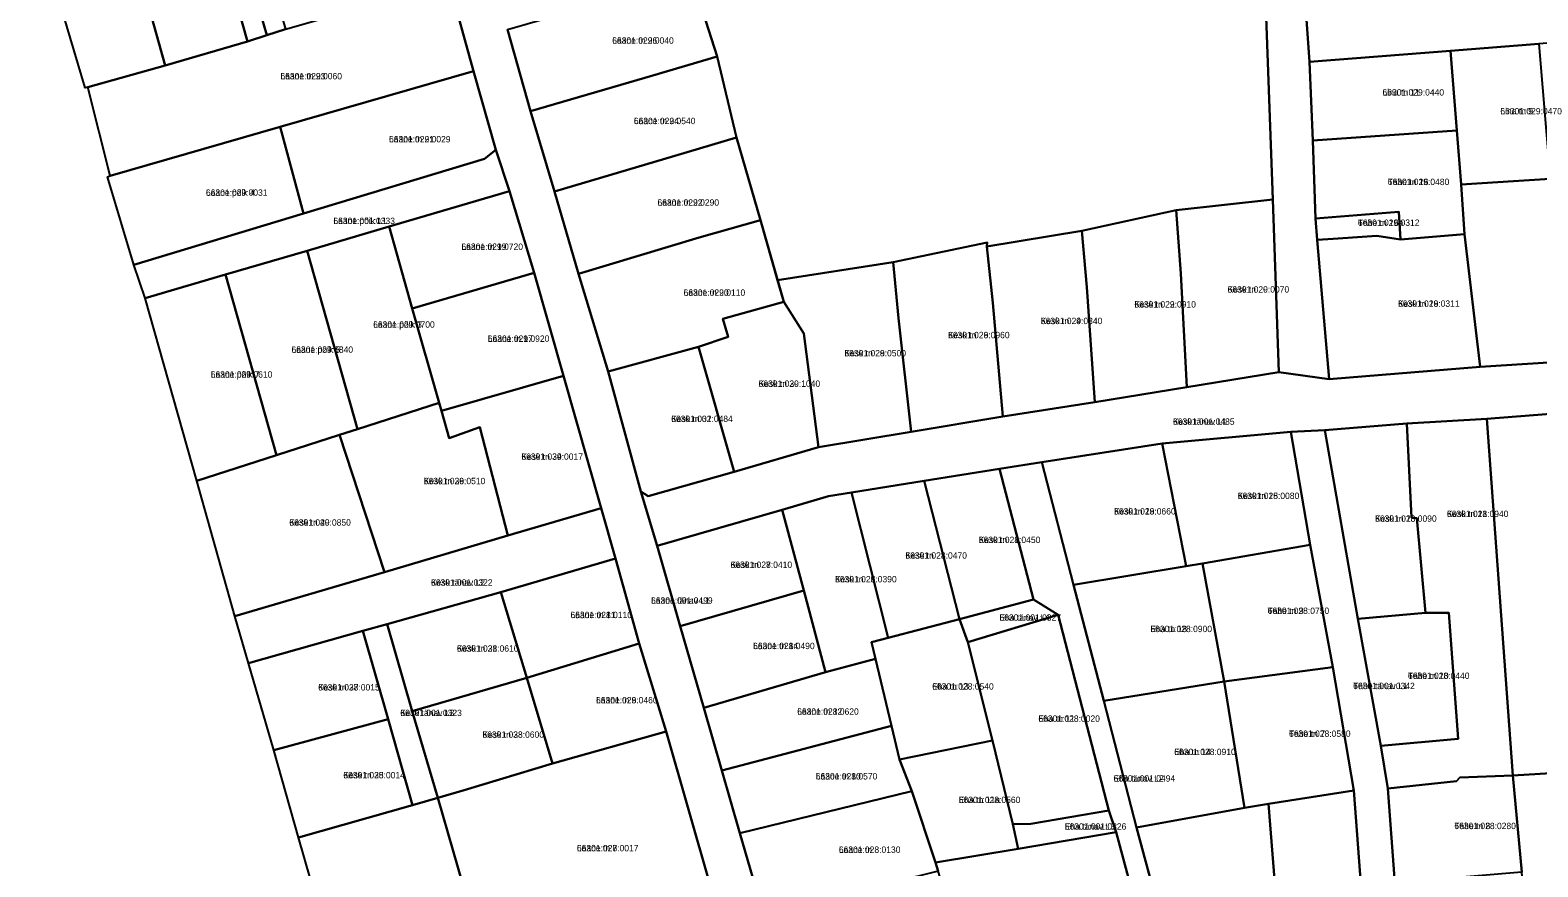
# Model space of a CAD drawing. Extents: x 632278 to 636344, y 6578401 to 6583362.
# Drawn here: x 632786.9 to 633142, y 6582179.7 to 6582376.8 of the extents above; entities that cross this region are included whole.
import ezdxf

# ---------------------------------------------------------------- set-up
doc = ezdxf.new("R2010")
doc.units = 0
for name, color, linetype in [('L_AADRESS', 7, 'Continuous'), ('PIIR', 7, 'Continuous'), ('TUNNUS', 7, 'Continuous')]:
    doc.layers.add(name, color=color, linetype=linetype)

msp = doc.modelspace()

# ---------------------------------------------------------------- linework, layer by layer
at = {"layer": 'PIIR'}
for points in [[(633075.2, 6582463.43), (633077.8, 6582386.33), (633070.2, 6582386.4), (633070.38, 6582382.02), (633077.94, 6582382.05), (633079.64, 6582336.91), (633056.87, 6582334.44), (633034.63, 6582329.54), (633012.24, 6582325.89), (633012.31, 6582326.81), (632990.17, 6582322.14), (632962.98, 6582317.93), (632958.95, 6582332.08), (632953.33, 6582351.51), (632948.72, 6582370.57), (632942.69, 6582389.52), (632937.03, 6582408.7), (632931.66, 6582427.68), (632925.7, 6582446.5), (632956.46, 6582453.19)], [(633075.2, 6582463.43), (633083.8, 6582464.53), (633084.6, 6582446.14), (633085.71, 6582421.36), (633086.82, 6582396.6), (633087.54, 6582379.34), (633088.25, 6582369.37), (633089.06, 6582350.85), (633089.65, 6582332.46), (633090.09, 6582327.4), (633092.89, 6582294.58), (633081.06, 6582296.22), (633079.64, 6582336.91), (633077.94, 6582382.05), (633077.8, 6582386.33)], [(632825.72, 6582418.14), (632830.04, 6582419.35), (632842.66, 6582375.6), (632838.14, 6582374.11)], [(632834.48, 6582420.6), (632847.1, 6582377.07), (632842.66, 6582375.6), (632830.04, 6582419.35)], [(632806.48, 6582412.41), (632825.72, 6582418.14), (632838.13, 6582374.11), (632818.75, 6582368.45)], [(632786.95, 6582406.91), (632806.48, 6582412.41), (632818.75, 6582368.45), (632800.56, 6582363.41), (632799.87, 6582363.22)], [(633087.54, 6582379.34), (633122.51, 6582382.07), (633141.41, 6582383.64), (633160.25, 6582385.06), (633179.47, 6582386.64), (633198.45, 6582388.1), (633235.16, 6582391.14), (633226.94, 6582379.94), (633205, 6582378.31), (633183.06, 6582376.69), (633161.16, 6582375.07), (633142.22, 6582373.59), (633121.45, 6582371.97), (633088.25, 6582369.37)], [(632800.56, 6582363.41), (632818.75, 6582368.45), (632838.13, 6582374.11), (632842.66, 6582375.6), (632847.1, 6582377.07), (632866.05, 6582382.47), (632866.64, 6582382.67), (632885.63, 6582387.98), (632891.4, 6582367.16), (632845.82, 6582354.06), (632805.79, 6582342.47)], [(632942.69, 6582389.52), (632948.72, 6582370.57), (632933.57, 6582366.11), (632904.77, 6582357.74), (632899.39, 6582376.93)], [(633122.93, 6582353.15), (633121.45, 6582371.97), (633142.22, 6582373.59), (633144.92, 6582341.77), (633123.93, 6582340.48)], [(632904.77, 6582357.74), (632933.57, 6582366.11), (632948.72, 6582370.57), (632953.33, 6582351.51), (632938.77, 6582347.18), (632910.47, 6582338.77)], [(633088.25, 6582369.37), (633121.45, 6582371.97), (633122.93, 6582353.15), (633089.06, 6582350.85)], [(632891.4, 6582367.16), (632896.61, 6582348.6), (632893.94, 6582346.51), (632851.32, 6582333.61), (632845.82, 6582354.06)], [(632845.82, 6582354.06), (632851.32, 6582333.61), (632811.34, 6582321.53), (632805.17, 6582342.29), (632805.79, 6582342.47)], [(633089.06, 6582350.85), (633122.93, 6582353.15), (633123.93, 6582340.48), (633124.72, 6582328.72), (633109.71, 6582327.48), (633109.27, 6582334.03), (633089.65, 6582332.46)], [(632811.34, 6582321.53), (632851.32, 6582333.61), (632893.94, 6582346.51), (632896.61, 6582348.6), (632899.87, 6582338.85), (632871.5, 6582330.53), (632852.15, 6582324.86), (632832.98, 6582319.24), (632814.01, 6582313.68)], [(632910.47, 6582338.77), (632938.77, 6582347.18), (632953.33, 6582351.51), (632958.95, 6582332.08), (632944.54, 6582327.94), (632916.11, 6582319.43)], [(633124.72, 6582328.72), (633123.93, 6582340.48), (633144.92, 6582341.77), (633163.87, 6582342.93), (633164.29, 6582336.96), (633166.86, 6582299.97), (633128.48, 6582297.49)], [(632871.5, 6582330.53), (632899.87, 6582338.85), (632905.62, 6582319.67), (632876.94, 6582311.27)], [(633056.87, 6582334.44), (633057.98, 6582319.51), (633059.37, 6582292.7), (633037.67, 6582289.17), (633035.82, 6582316.25), (633034.63, 6582329.54)], [(633079.64, 6582336.91), (633081.06, 6582296.22), (633059.37, 6582292.7), (633057.98, 6582319.51), (633056.87, 6582334.44)], [(633090.09, 6582327.4), (633089.65, 6582332.46), (633109.27, 6582334.03), (633109.71, 6582327.48), (633104.1, 6582328.35), (633093.85, 6582327.63)], [(632852.15, 6582324.86), (632871.5, 6582330.53), (632876.94, 6582311.27), (632883.31, 6582289.02), (632864.03, 6582282.82)], [(632916.11, 6582319.43), (632944.54, 6582327.94), (632958.95, 6582332.08), (632964.43, 6582312.83), (632950.05, 6582308.81), (632951.3, 6582304.54), (632944.39, 6582302.26), (632923.06, 6582296.42)], [(633034.63, 6582329.54), (633035.82, 6582316.25), (633037.67, 6582289.17), (633016.06, 6582285.79), (633013.67, 6582312.62), (633012.24, 6582325.89)], [(633092.89, 6582294.58), (633090.09, 6582327.4), (633093.85, 6582327.63), (633104.1, 6582328.35), (633109.71, 6582327.48), (633124.72, 6582328.72), (633128.48, 6582297.49)], [(632832.98, 6582319.24), (632852.15, 6582324.86), (632864.03, 6582282.82), (632859.83, 6582281.47), (632844.98, 6582276.7)], [(633012.31, 6582326.81), (633012.24, 6582325.89), (633013.67, 6582312.62), (633016.06, 6582285.79), (632994.46, 6582282.19), (632991.47, 6582308.98), (632990.17, 6582322.14)], [(632990.17, 6582322.14), (632991.47, 6582308.98), (632994.46, 6582282.19), (632972.6, 6582278.59), (632969.19, 6582305.33), (632964.43, 6582312.83), (632962.98, 6582317.93)], [(632814.01, 6582313.68), (632832.98, 6582319.24), (632844.98, 6582276.7), (632826.17, 6582270.66)], [(632883.31, 6582289.02), (632876.94, 6582311.27), (632905.62, 6582319.67), (632912.56, 6582295.38), (632883.84, 6582287.12)], [(632944.39, 6582302.26), (632951.3, 6582304.54), (632950.05, 6582308.81), (632964.43, 6582312.83), (632969.19, 6582305.33), (632972.6, 6582278.59), (632952.77, 6582272.75)], [(632930.8, 6582268.16), (632923.06, 6582296.42), (632944.39, 6582302.26), (632952.77, 6582272.75), (632932.49, 6582267.03)], [(632883.84, 6582287.12), (632912.56, 6582295.38), (632921.43, 6582264.25), (632899.47, 6582257.75), (632892.85, 6582283.28), (632885.66, 6582280.75)], [(632859.83, 6582281.47), (632864.03, 6582282.82), (632883.31, 6582289.02), (632883.84, 6582287.12), (632885.66, 6582280.75), (632892.85, 6582283.28), (632899.47, 6582257.75), (632870.39, 6582249.16)], [(633130.03, 6582285.3), (633168.04, 6582288.21), (633174.79, 6582203.63), (633136.14, 6582201.28)], [(633122.89, 6582199.92), (633106.71, 6582198.2), (633105.06, 6582208.24), (633123.23, 6582209.86), (633121.03, 6582239.56), (633115.58, 6582239.54), (633113.49, 6582261.84), (633112.25, 6582262.05), (633111.15, 6582284.13), (633130.03, 6582285.3), (633136.14, 6582201.28), (633123.65, 6582200.81)], [(632844.98, 6582276.7), (632859.83, 6582281.47), (632870.39, 6582249.16), (632835.19, 6582238.75), (632826.17, 6582270.66)], [(633088.38, 6582255.59), (633063.04, 6582251.21), (633059.24, 6582250.55), (633053.57, 6582279.48), (633083.84, 6582282.22)], [(633083.84, 6582282.22), (633091.83, 6582282.57), (633099.63, 6582238.17), (633105.06, 6582208.24), (633106.71, 6582198.2), (633108.33, 6582175.99), (633109.76, 6582156.19), (633111.72, 6582133.82), (633113.23, 6582113.59), (633105.08, 6582112.97), (633101.88, 6582154.89), (633098.72, 6582197.72), (633093.73, 6582226.74), (633088.38, 6582255.59)], [(633113.49, 6582261.84), (633115.58, 6582239.54), (633099.63, 6582238.17), (633091.83, 6582282.57), (633111.15, 6582284.13), (633112.25, 6582262.05)], [(633025.23, 6582275.04), (633053.57, 6582279.48), (633059.24, 6582250.55), (633032.69, 6582246.19)], [(633023.24, 6582242.75), (633015.25, 6582273.48), (633025.23, 6582275.04), (633032.69, 6582246.19), (633039.78, 6582218.84), (633047.5, 6582188.99), (633056.74, 6582154.68), (633068.96, 6582107.55), (633064.58, 6582105.78), (633059.45, 6582125.11), (633053.02, 6582149.29), (633047.89, 6582168.61), (633042.75, 6582187.94), (633040.99, 6582193.04), (633029.03, 6582239.07)], [(632980.36, 6582267.88), (632997.47, 6582270.63), (633005.79, 6582238.12), (632989, 6582233.65)], [(633023.24, 6582242.75), (633005.79, 6582238.12), (632997.47, 6582270.63), (633015.25, 6582273.48)], [(632985.13, 6582232.63), (632986.04, 6582228.76), (632974.28, 6582225.62), (632969.13, 6582244.84), (632964.03, 6582263.87), (632974.98, 6582267.02), (632980.36, 6582267.88), (632989, 6582233.65)], [(632835.19, 6582238.75), (632870.39, 6582249.16), (632899.47, 6582257.75), (632921.43, 6582264.25), (632924.83, 6582252.36), (632897.82, 6582244.42), (632871.01, 6582236.89), (632865.27, 6582235.37), (632838.38, 6582227.69)], [(632934.6, 6582255.36), (632964.03, 6582263.87), (632969.13, 6582244.84), (632940.04, 6582236.42)], [(632903.9, 6582224.29), (632897.82, 6582244.42), (632924.83, 6582252.36), (632930.41, 6582232.36)], [(633063.04, 6582251.21), (633088.38, 6582255.59), (633093.73, 6582226.74), (633068.12, 6582223.43)], [(633032.69, 6582246.19), (633059.24, 6582250.55), (633063.04, 6582251.21), (633068.12, 6582223.43), (633039.78, 6582218.84)], [(632871.01, 6582236.89), (632897.82, 6582244.42), (632903.9, 6582224.29), (632876.89, 6582216.43)], [(632940.04, 6582236.42), (632969.13, 6582244.84), (632974.28, 6582225.62), (632945.57, 6582217.2)], [(633005.79, 6582238.12), (633023.24, 6582242.75), (633029.03, 6582239.07), (633007.78, 6582232.67)], [(632989.77, 6582212.99), (632986.04, 6582228.76), (632985.13, 6582232.63), (632989, 6582233.65), (633005.79, 6582238.12), (633007.78, 6582232.67), (633013.63, 6582209.54), (632991.66, 6582205)], [(633029.03, 6582239.07), (633040.99, 6582193.04), (633022.6, 6582189.84), (633018.39, 6582189.79), (633013.63, 6582209.54), (633007.78, 6582232.67)], [(633099.63, 6582238.17), (633115.58, 6582239.54), (633121.03, 6582239.56), (633123.23, 6582209.86), (633105.06, 6582208.24)], [(632838.38, 6582227.69), (632865.27, 6582235.37), (632871.26, 6582214.56), (632844.33, 6582207.19)], [(632871.01, 6582236.89), (632876.89, 6582216.43), (632882.98, 6582195.99), (632877.03, 6582194.25), (632871.26, 6582214.56), (632865.27, 6582235.37)], [(632903.9, 6582224.29), (632930.41, 6582232.36), (632936.71, 6582211.65), (632910, 6582204.12)], [(632945.57, 6582217.2), (632974.28, 6582225.62), (632986.04, 6582228.76), (632989.77, 6582212.99), (632949.82, 6582202.4)], [(632876.89, 6582216.43), (632903.9, 6582224.29), (632910, 6582204.12), (632889.18, 6582197.84), (632882.98, 6582195.99)], [(633072.97, 6582193.64), (633068.12, 6582223.43), (633093.73, 6582226.74), (633098.72, 6582197.72), (633078.59, 6582194.56)], [(633039.78, 6582218.84), (633068.12, 6582223.43), (633072.97, 6582193.64), (633047.5, 6582188.99)], [(632871.26, 6582214.56), (632877.03, 6582194.25), (632850.11, 6582186.65), (632844.33, 6582207.19)], [(632882.98, 6582195.99), (632889.18, 6582197.84), (632910, 6582204.12), (632936.71, 6582211.65), (632947.12, 6582175.45), (632948.55, 6582170.62), (632894.77, 6582155.17)], [(632949.82, 6582202.4), (632989.77, 6582212.99), (632991.66, 6582205), (632994.63, 6582197.57), (632954.09, 6582187.66)], [(632994.63, 6582197.57), (632991.66, 6582205), (633013.63, 6582209.54), (633018.39, 6582189.79), (633019.64, 6582183.99), (633000.15, 6582180.73)], [(633141.54, 6582136.13), (633139.71, 6582158.69), (633138.24, 6582178.49), (633136.14, 6582201.28), (633174.79, 6582203.63), (633181.02, 6582118.81), (633143.13, 6582115.89)], [(633106.71, 6582198.2), (633122.89, 6582199.92), (633123.65, 6582200.81), (633136.14, 6582201.28), (633138.24, 6582178.49), (633108.33, 6582175.99)], [(632850.11, 6582186.65), (632877.03, 6582194.25), (632882.98, 6582195.99), (632894.77, 6582155.17), (632888.7, 6582153.44), (632861.94, 6582145.76)], [(633000.15, 6582180.73), (633000.77, 6582178.76), (632959.63, 6582168.5), (632954.09, 6582187.66), (632994.63, 6582197.57)], [(633081.55, 6582157.04), (633078.59, 6582194.56), (633098.72, 6582197.72), (633101.88, 6582154.89), (633082.07, 6582153.21)], [(633018.39, 6582189.79), (633022.6, 6582189.84), (633040.99, 6582193.04), (633042.75, 6582187.94), (633019.64, 6582183.99)], [(633072.97, 6582193.64), (633078.59, 6582194.56), (633081.55, 6582157.04), (633056.74, 6582154.68), (633047.5, 6582188.99)], [(633000.77, 6582178.76), (633000.15, 6582180.73), (633019.64, 6582183.99), (633042.75, 6582187.94), (633047.89, 6582168.61), (633006.21, 6582161.49)]]:
    msp.add_lwpolyline(points, close=True, dxfattribs=at)
for points in [[(632947.12, 6582175.45), (632936.71, 6582211.65), (632930.41, 6582232.36), (632924.83, 6582252.36), (632921.43, 6582264.25), (632912.56, 6582295.38), (632905.62, 6582319.67), (632899.87, 6582338.85), (632896.61, 6582348.6), (632891.4, 6582367.16), (632885.63, 6582387.98)], [(632899.39, 6582376.93), (632904.77, 6582357.74), (632910.47, 6582338.77), (632916.11, 6582319.43), (632923.06, 6582296.42), (632930.8, 6582268.16), (632934.6, 6582255.36), (632940.04, 6582236.42), (632945.57, 6582217.2), (632949.82, 6582202.4), (632954.09, 6582187.66), (632959.63, 6582168.5)], [(633168.04, 6582288.21), (633130.03, 6582285.3), (633111.15, 6582284.13), (633091.83, 6582282.57), (633083.84, 6582282.22), (633053.57, 6582279.48), (633025.23, 6582275.04), (633015.25, 6582273.48), (632997.47, 6582270.63), (632980.36, 6582267.88), (632974.98, 6582267.02), (632964.03, 6582263.87), (632934.6, 6582255.36), (632930.8, 6582268.16), (632932.49, 6582267.03), (632952.77, 6582272.75), (632972.6, 6582278.59), (632994.46, 6582282.19), (633016.06, 6582285.79), (633037.67, 6582289.17), (633059.37, 6582292.7), (633081.06, 6582296.22), (633092.89, 6582294.58), (633128.48, 6582297.49), (633166.86, 6582299.97)]]:
    msp.add_lwpolyline(points, dxfattribs=at)

# ---------------------------------------------------------------- texts
at = {"layer": 'L_AADRESS'}
for s, p in [('Lääne tn 26', (632924.03, 6582373.63)), ('Lääne tn 23', (632845.89, 6582365.23)), ('Lina tn 11', (633105.44, 6582361.41)), ('Lääne tn 24', (632929.13, 6582354.67)), ('Lina tn 9', (633133.19, 6582356.97)), ('Lääne tn 21', (632871.46, 6582350.38)), ('Tähe tn 16', (633106.67, 6582340.32)), ('Lääne põik 4', (632828.35, 6582337.79)), ('Lääne tn 22', (632934.7, 6582335.47)), ('Lääne põik L1', (632858.36, 6582331.14)), ('Tähe tn 16a', (633099.65, 6582330.71)), ('Lääne tn 19', (632888.52, 6582325.06)), ('Kesk tn 20', (633068.96, 6582315)), ('Lääne tn 20', (632940.85, 6582314.25)), ('Kesk tn 22', (633047, 6582311.48)), ('Kesk tn 18', (633109.1, 6582311.65)), ('Kesk tn 24', (633024.96, 6582307.57)), ('Lääne põik 3', (632867.73, 6582306.72)), ('Kesk tn 26', (633003.12, 6582304.25)), ('Lääne põik 5', (632848.5, 6582300.81)), ('Lääne tn 17', (632894.73, 6582303.4)), ('Kesk tn 28', (632978.72, 6582299.98)), ('Lääne põik 7', (632829.49, 6582294.97)), ('Kesk tn 30', (632958.5, 6582292.8)), ('Kesk tn 32', (632937.92, 6582284.52)), ('Kesk tänav L1', (633056.1, 6582283.86)), ('Kesk tn 34', (632902.64, 6582275.61)), ('Kesk tn 36', (632879.65, 6582269.87)), ('Kesk tn 15', (633071.34, 6582266.38)), ('Kesk tn 19', (633042.23, 6582262.73)), ('Kesk tn 11', (633120.6, 6582262.14)), ('Kesk tn 40', (632847.98, 6582260.11)), ('Kesk tn 13', (633103.7, 6582261.02)), ('Kesk tn 21', (633010.36, 6582256.01)), ('Kesk tn 23', (632993.07, 6582252.33)), ('Kesk tn 27', (632951.9, 6582250.15)), ('Kesk tänav L2', (632881.35, 6582245.97)), ('Kesk tn 25', (632976.52, 6582246.74)), ('Lääne tänav L1', (632933.18, 6582241.72)), ('Lääne tn 11', (632914.2, 6582238.32)), ('Eha tänav L4', (633015.23, 6582237.71)), ('Tähe tn 9', (633078.38, 6582239.31)), ('Eha tn 18', (633050.79, 6582235.03)), ('Kesk tn 31', (632887.46, 6582230.43)), ('Lääne tn 14', (632957.21, 6582231.02)), ('Tähe tn 10', (633111.43, 6582224)), ('Kesk tn 37', (632854.78, 6582221.28)), ('Eha tn 13', (632999.38, 6582221.5)), ('Tähe tänav L1', (633098.54, 6582221.6)), ('Kesk tänav L3', (632874.12, 6582215.26)), ('Lääne tn 9', (632920.22, 6582218.24)), ('Lääne tn 12', (632967.6, 6582215.58)), ('Eha tn 11', (633024.39, 6582213.91)), ('Kesk tn 33', (632893.47, 6582210.14)), ('Tähe tn 7', (633083.42, 6582210.36)), ('Eha tn 14', (633056.38, 6582206.07)), ('Kesk tn 35', (632860.7, 6582200.6)), ('Lääne tn 10', (632971.97, 6582200.32)), ('Eha tänav L2', (633042.11, 6582199.83)), ('Eha tn 11a', (633005.65, 6582194.77)), ('Eha tänav L3', (633030.61, 6582188.51)), ('Tähe tn 8', (633122.36, 6582188.63)), ('Lääne tn 7', (632915.72, 6582183.41)), ('Lääne tn 8', (632977.41, 6582183.04))]:
    msp.add_text(s, height=1.5, dxfattribs=at).set_placement(p)
at = {"layer": 'TUNNUS'}
for s, p in [('66301:029:0040', (632924.03, 6582373.63)), ('66301:029:0060', (632845.89, 6582365.23)), ('66301:029:0440', (633105.44, 6582361.41)), ('66301:029:0540', (632929.13, 6582354.67)), ('66301:029:0470', (633133.19, 6582356.97)), ('66301:029:0029', (632871.46, 6582350.38)), ('66301:029:0480', (633106.67, 6582340.32)), ('66301:029:0031', (632828.35, 6582337.79)), ('66301:029:0290', (632934.7, 6582335.47)), ('66301:001:0333', (632858.36, 6582331.14)), ('66301:029:0312', (633099.65, 6582330.71)), ('66301:029:0720', (632888.52, 6582325.06)), ('66301:029:0070', (633068.96, 6582315)), ('66301:029:0110', (632940.85, 6582314.25)), ('66301:029:0910', (633047, 6582311.48)), ('66301:029:0311', (633109.1, 6582311.65)), ('66301:029:0700', (632867.73, 6582306.72)), ('66301:029:0960', (633003.12, 6582304.25)), ('66301:029:0340', (633024.96, 6582307.57)), ('66301:029:0840', (632848.5, 6582300.81)), ('66301:029:0920', (632894.73, 6582303.4)), ('66301:029:0500', (632978.72, 6582299.98)), ('66301:029:0610', (632829.49, 6582294.97)), ('66301:029:1040', (632958.5, 6582292.8)), ('66301:001:0484', (632937.92, 6582284.52)), ('66301:001:0485', (633056.1, 6582283.86)), ('66301:029:0017', (632902.64, 6582275.61)), ('66301:029:0510', (632879.65, 6582269.87)), ('66301:028:0080', (633071.34, 6582266.38)), ('66301:028:0660', (633042.23, 6582262.73)), ('66301:028:0940', (633120.6, 6582262.14)), ('66301:029:0850', (632847.98, 6582260.11)), ('66301:028:0090', (633103.7, 6582261.02)), ('66301:028:0450', (633010.36, 6582256.01)), ('66301:028:0470', (632993.07, 6582252.33)), ('66301:028:0410', (632951.9, 6582250.15)), ('66301:001:0322', (632881.35, 6582245.97)), ('66301:028:0390', (632976.52, 6582246.74)), ('66301:001:0499', (632933.18, 6582241.72)), ('66301:028:0110', (632914.2, 6582238.32)), ('66301:001:0327', (633015.23, 6582237.71)), ('66301:028:0750', (633078.38, 6582239.31)), ('66301:028:0900', (633050.79, 6582235.03)), ('66301:028:0610', (632887.46, 6582230.43)), ('66301:028:0490', (632957.21, 6582231.02)), ('66301:028:0440', (633111.43, 6582224)), ('66301:028:0015', (632854.78, 6582221.28)), ('66301:028:0540', (632999.38, 6582221.5)), ('66301:001:0342', (633098.54, 6582221.6)), ('66301:001:0323', (632874.12, 6582215.26)), ('66301:028:0460', (632920.22, 6582218.24)), ('66301:028:0620', (632967.6, 6582215.58)), ('66301:028:0020', (633024.39, 6582213.91)), ('66301:028:0600', (632893.47, 6582210.14)), ('66301:028:0580', (633083.42, 6582210.36)), ('66301:028:0910', (633056.38, 6582206.07)), ('66301:028:0014', (632860.7, 6582200.6)), ('66301:028:0570', (632971.97, 6582200.32)), ('66301:001:0494', (633042.11, 6582199.83)), ('66301:028:0560', (633005.65, 6582194.77)), ('66301:001:0326', (633030.61, 6582188.51)), ('66301:028:0280', (633122.36, 6582188.63)), ('66301:028:0017', (632915.72, 6582183.41)), ('66301:028:0130', (632977.41, 6582183.04))]:
    msp.add_text(s, height=1.5, dxfattribs=at).set_placement(p)

doc.saveas('drawing.dxf')
